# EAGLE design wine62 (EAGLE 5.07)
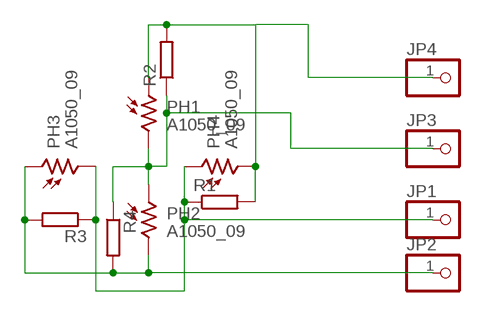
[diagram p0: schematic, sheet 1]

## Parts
JP1  PINHD-1X11MM6  [1X1MM8]
JP2  PINHD-1X11MM6  [1X1MM8]
JP3  PINHD-1X11MM6  [1X1MM8]
JP4  PINHD-1X11MM6  [1X1MM8]
PH1  A1050_09  [T0-46-A10XX]
PH2  A1050_09  [T0-46-A10XX]
PH3  A1050_09  [T0-46-A10XX]
PH4  A1050_09  [T0-46-A10XX]
R1  R-EU_R1206  [R1206]
R2  R-EU_R1206  [R1206]
R3  R-EU_R1206  [R1206]
R4  R-EU_R1206  [R1206]

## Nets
N$1: JP1.1 PH3.2 PH4.1 R1.1 R3.1
N$2: JP3.1 PH1.2 PH2.1 R2.1 R4.1
N$3: JP4.1 PH1.1 PH4.2 R1.2 R2.2
N$4: JP2.1 PH2.2 PH3.1 R3.2 R4.2

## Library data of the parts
JP1-JP4 = pinhead:PINHD-1X1: PIN HEADER
PH1-PH4 = photo-elements:A10: Sensor Robust Light Sensing Applications
R1-R4 = rcl:R-EU_: RESISTOR, European symbol

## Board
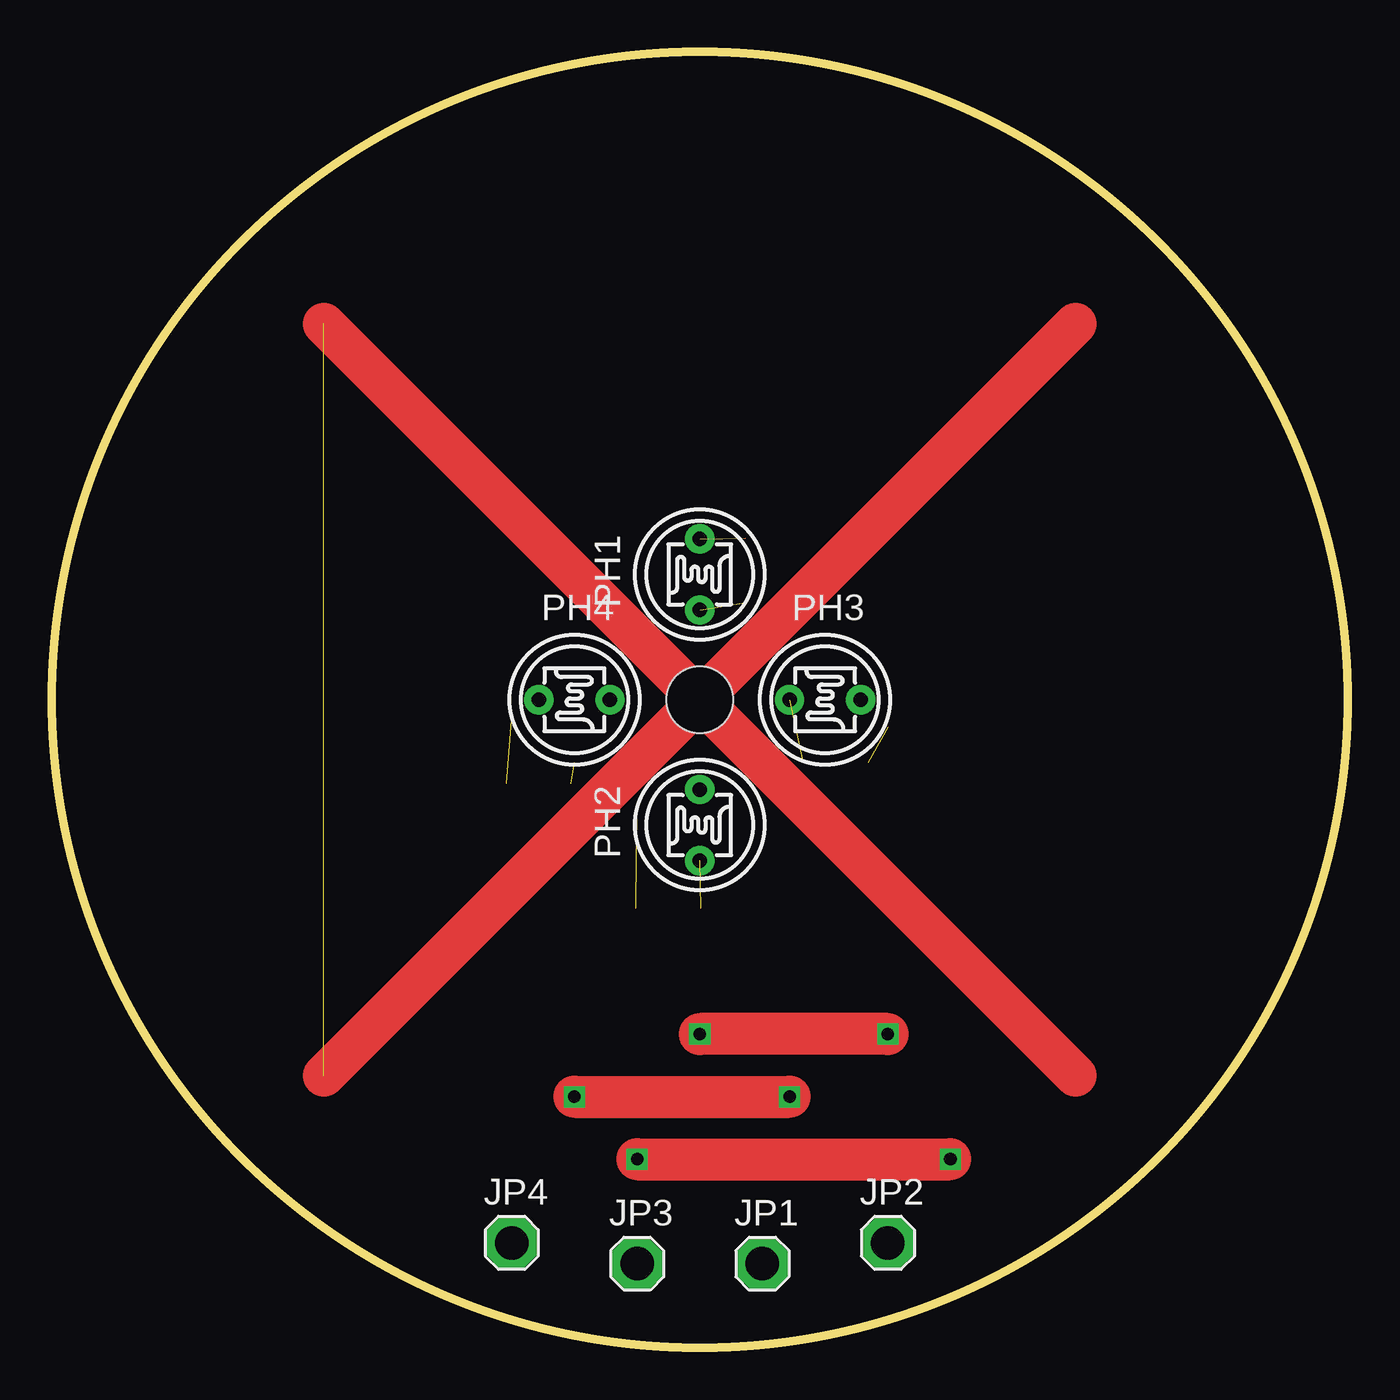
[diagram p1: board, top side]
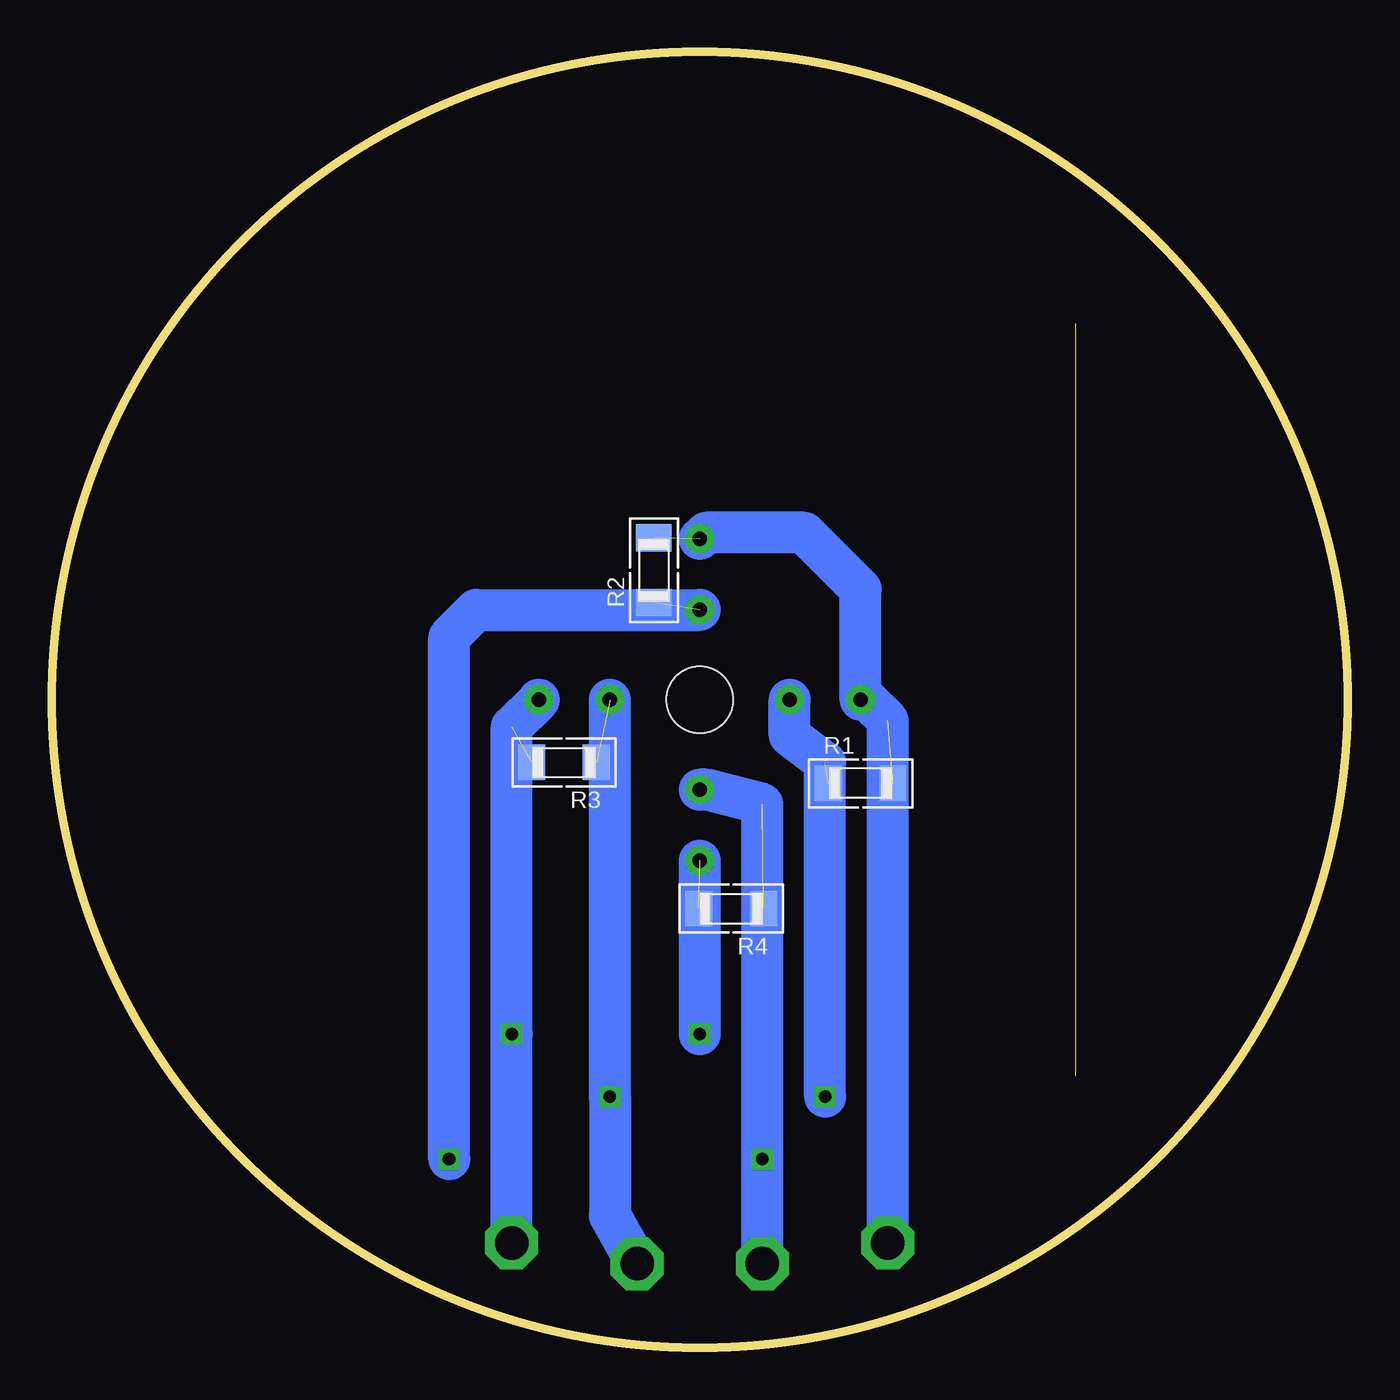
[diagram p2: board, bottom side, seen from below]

Size 62 x 62 mm. Coordinates in mm from the lower left corner, seen from the top.
Outline: circle at 31,31 radius 31
Copper layers (1*16): Top 0.035mm / dielectric 1.5mm / Bottom 0.035mm
Design rules "default": minimum track width 10mil, minimum drill 20mil, track to track 8mil, track to pad 8mil, pad to pad 8mil, via to via 8mil, smd to smd 8mil, copper to edge 40mil, drill to drill 8mil, minimum pad ring 1mil, minimum via ring 8mil, stop-mask expansion 4mil, vias tented up to drill 0mil, thermal gap 10mil
Holes 3.2 mm at 31,31

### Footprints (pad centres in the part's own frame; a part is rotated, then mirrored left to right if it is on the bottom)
1X1MM8 = drill 1.6 pad 2.54 octagon: 1 0,0
T0-46-A10XX = drill 0.7 pad 1.4 round: 1 -1.7,0; 2 1.7,0
R1206 = smd 1.3 x 1.7: 1 -1.55,0; 2 1.55,0

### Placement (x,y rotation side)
JP1  34,4 0 top
JP2  40,5 0 top
JP3  28,4 0 top
JP4  22,5 0 top
PH1  31,37 270 top
PH2  31,25 270 top
PH3  37,31 180 top
PH4  25,31 180 top
R1  23.3,27 0 bottom
R2  33.2,37.2 90 bottom
R3  37.5,28 180 bottom
R4  29.5,21 180 bottom

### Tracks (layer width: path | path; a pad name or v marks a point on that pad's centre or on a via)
N$1  (via drill 0.6)  (2 unrouted)
  Top 2: v25,12 v35.3,12
  Bottom 2: PH4.1 26.7,29.3 25,28 v25,12 | JP1.1 35.3,6.3 v35.3,12 PH3.2
N$2  (via drill 0.6)  (2 unrouted)
  Top 2: v28,9 v43,9
  Bottom 2: PH1.2 41.7,35.3 43,34 v43,9 | PH2.1 30.7,26.7 28,26 v28,9 JP3.1
N$3  (2 unrouted)
  Bottom 2: JP4.1 22,30 23,31 PH4.2 23.3,36.3 26,39 30.7,39 PH1.1
N$4  (via drill 0.6)  (2 unrouted)
  Top 2: v40,15 v31,15
  Bottom 2: JP2.1 v40,15 40,29.7 PH3.1 | v31,15 PH2.2
N$7  (1 unrouted)
  Top 2: 13,49 49,13 | 13,13 49,49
